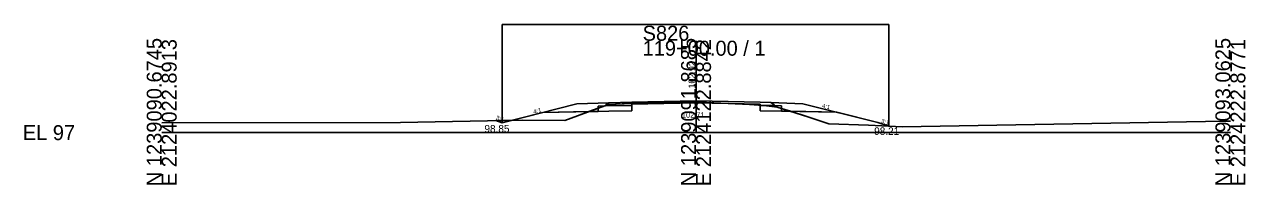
# Model space of a CAD drawing. Extents: x 2119282 to 2119710, y 1215030 to 1220057.
# Drawn here: x 2119381.9 to 2119610.4, y 1217530.1 to 1217560 of the extents above; entities that cross this region are included whole.
import ezdxf

# ---------------------------------------------------------------- set-up
doc = ezdxf.new("R2010")
doc.units = 0
for name, color, linetype in [('XS_CELL', 7, 'Continuous'), ('XS_M_DITCH', 7, 'Continuous'), ('XS_M_SHAPES_EARTHWORK', 7, 'Continuous'), ('XS_P_FINISHED_GRADE', 7, 'Continuous'), ('XS_P_FINISHED_GRADE_ELEV_TX', 7, 'Continuous'), ('XS_P_SUBGRADE_GRANULAR', 7, 'Continuous'), ('XS_P_SUBGRADE_PAVEMENT', 7, 'Continuous'), ('XS_P_TX_DCH', 7, 'Continuous'), ('XS_P_TX_FS_BS', 7, 'Continuous'), ('XS_X_GROUND', 7, 'Continuous'), ('XS_X_GROUND_TX', 7, 'Continuous')]:
    doc.layers.add(name, color=color, linetype=linetype)

msp = doc.modelspace()

# ---------------------------------------------------------------- linework, layer by layer
at = {"layer": 'XS_CELL'}
for p, q in [((2119507.6, 1217539.8), (2119507.6, 1217556.97)), ((2119407.6, 1217539.8), (2119507.6, 1217539.8)), ((2119507.6, 1217539.8), (2119607.6, 1217539.8))]:
    msp.add_line(p, q, dxfattribs=at)
at = {"layer": 'XS_M_DITCH'}
for p, q in [((2119471.29, 1217541.66), (2119471.29, 1217560.01)), ((2119471.29, 1217560.01), (2119543.67, 1217560.01)), ((2119543.67, 1217541.01), (2119543.67, 1217560.01))]:
    msp.add_line(p, q, dxfattribs=at)
at = {"layer": 'XS_M_SHAPES_EARTHWORK'}
for p, q in [((2119489.29, 1217544.36), (2119487.56, 1217543.74)), ((2119490.52, 1217544.79), (2119489.29, 1217544.36)), ((2119489.29, 1217543.77), (2119489.29, 1217544.36)), ((2119489.29, 1217544.36), (2119489.29, 1217543.77)), ((2119490.64, 1217544.8), (2119490.52, 1217544.79)), ((2119495.6, 1217544.9), (2119490.64, 1217544.8)), ((2119490.64, 1217544.8), (2119495.6, 1217544.9)), ((2119490.67, 1217544.85), (2119490.64, 1217544.8)), ((2119491.23, 1217545.05), (2119490.67, 1217544.85)), ((2119495.6, 1217545.25), (2119491.23, 1217545.05)), ((2119495.6, 1217543.9), (2119495.6, 1217544.9)), ((2119520.17, 1217544.89), (2119519.6, 1217544.92)), ((2119519.6, 1217544.92), (2119519.6, 1217544.9)), ((2119519.6, 1217544.9), (2119519.6, 1217543.9)), ((2119520.17, 1217544.89), (2119519.6, 1217544.9)), ((2119519.6, 1217544.9), (2119519.6, 1217543.9)), ((2119519.6, 1217544.9), (2119520.17, 1217544.89)), ((2119520.23, 1217544.89), (2119520.17, 1217544.89)), ((2119520.79, 1217544.83), (2119520.23, 1217544.89)), ((2119520.79, 1217544.83), (2119520.23, 1217544.89)), ((2119522.79, 1217544.57), (2119520.79, 1217544.83)), ((2119522.79, 1217544.57), (2119520.79, 1217544.83)), ((2119523.6, 1217544.31), (2119522.79, 1217544.57)), ((2119523.6, 1217544.31), (2119522.79, 1217544.57)), ((2119525.27, 1217543.79), (2119523.6, 1217544.31)), ((2119523.6, 1217544.31), (2119523.6, 1217543.82)), ((2119523.6, 1217543.82), (2119523.6, 1217544.31)), ((2119523.6, 1217543.82), (2119523.6, 1217544.31)), ((2119473.05, 1217542.1), (2119470.13, 1217542.04)), ((2119470.13, 1217542.04), (2119471.29, 1217541.66)), ((2119471.29, 1217541.66), (2119473.05, 1217542.1)), ((2119478.93, 1217543.57), (2119473.05, 1217542.1)), ((2119473.05, 1217542.1), (2119475.03, 1217542.13)), ((2119475.03, 1217542.13), (2119483.05, 1217542.1)), ((2119487.56, 1217543.74), (2119478.93, 1217543.57)), ((2119483.05, 1217542.1), (2119485.42, 1217542.97)), ((2119485.42, 1217542.97), (2119487.56, 1217543.74)), ((2119487.56, 1217543.74), (2119489.29, 1217543.77)), ((2119489.29, 1217543.77), (2119491.29, 1217543.81)), ((2119491.29, 1217543.81), (2119495.6, 1217543.9)), ((2119519.6, 1217543.9), (2119523.6, 1217543.82)), ((2119519.6, 1217543.9), (2119523.6, 1217543.82)), ((2119523.6, 1217543.82), (2119525.27, 1217543.79)), ((2119533.97, 1217543.61), (2119525.27, 1217543.79)), ((2119525.27, 1217543.79), (2119528.51, 1217542.75)), ((2119528.51, 1217542.75), (2119532.45, 1217541.46)), ((2119541.6, 1217541.7), (2119533.97, 1217543.61)), ((2119543.67, 1217541.01), (2119541.6, 1217541.7)), ((2119532.45, 1217541.46), (2119539.86, 1217541.18)), ((2119539.86, 1217541.18), (2119543.67, 1217541.01))]:
    msp.add_line(p, q, dxfattribs=at)
for points in [[(2119495.6, 1217544.9), (2119495.6, 1217545.15), (2119495.6, 1217545.25)], [(2119520.23, 1217544.89), (2119520.17, 1217544.89), (2119519.6, 1217544.9)]]:
    msp.add_lwpolyline(points, dxfattribs=at)
at = {"layer": 'XS_P_FINISHED_GRADE'}
for p, q in [((2119485.29, 1217545.16), (2119471.29, 1217541.66)), ((2119491.29, 1217545.4), (2119485.29, 1217545.16)), ((2119495.6, 1217545.48), (2119491.29, 1217545.4)), ((2119507.6, 1217545.72), (2119495.6, 1217545.48)), ((2119507.6, 1217545.72), (2119519.6, 1217545.48)), ((2119519.6, 1217545.48), (2119521.6, 1217545.44)), ((2119521.6, 1217545.44), (2119527.6, 1217545.2)), ((2119527.6, 1217545.2), (2119541.6, 1217541.7)), ((2119471.29, 1217541.66), (2119470.13, 1217542.04)), ((2119541.6, 1217541.7), (2119543.67, 1217541.01))]:
    msp.add_line(p, q, dxfattribs=at)
at = {"layer": 'XS_P_SUBGRADE_GRANULAR'}
for p, q in [((2119490.64, 1217544.8), (2119489.29, 1217544.75)), ((2119489.29, 1217543.77), (2119489.29, 1217544.75)), ((2119495.6, 1217543.9), (2119495.61, 1217544.9)), ((2119519.6, 1217543.9), (2119519.59, 1217544.9)), ((2119522.26, 1217544.85), (2119523.6, 1217544.79)), ((2119523.6, 1217543.82), (2119523.6, 1217544.79)), ((2119491.29, 1217543.81), (2119478.93, 1217543.57)), ((2119495.6, 1217543.9), (2119491.29, 1217543.81)), ((2119519.6, 1217543.9), (2119523.6, 1217543.82)), ((2119523.6, 1217543.82), (2119533.97, 1217543.61))]:
    msp.add_line(p, q, dxfattribs=at)
at = {"layer": 'XS_P_SUBGRADE_PAVEMENT'}
for p, q in [((2119490.79, 1217545.05), (2119490.64, 1217544.8)), ((2119495.61, 1217544.9), (2119490.64, 1217544.8)), ((2119491.29, 1217545.4), (2119490.79, 1217545.05)), ((2119507.6, 1217545.39), (2119495.61, 1217545.15)), ((2119495.61, 1217544.9), (2119495.61, 1217545.15)), ((2119507.6, 1217545.39), (2119519.6, 1217545.15)), ((2119519.59, 1217544.9), (2119519.6, 1217545.15)), ((2119519.59, 1217544.9), (2119522.26, 1217544.85)), ((2119521.6, 1217545.44), (2119522.11, 1217545.1)), ((2119522.11, 1217545.1), (2119522.26, 1217544.85))]:
    msp.add_line(p, q, dxfattribs=at)
at = {"layer": 'XS_X_GROUND'}
for p, q in [((2119485.42, 1217542.97), (2119491.23, 1217545.05)), ((2119491.23, 1217545.05), (2119496.32, 1217545.28)), ((2119496.32, 1217545.28), (2119507.6, 1217545.51)), ((2119507.6, 1217545.51), (2119508.25, 1217545.52)), ((2119508.25, 1217545.52), (2119517.59, 1217545.03)), ((2119517.59, 1217545.03), (2119520.17, 1217544.89)), ((2119520.17, 1217544.89), (2119520.79, 1217544.83)), ((2119520.79, 1217544.83), (2119522.79, 1217544.57)), ((2119522.79, 1217544.57), (2119528.51, 1217542.75)), ((2119407.6, 1217541.65), (2119452.32, 1217541.72)), ((2119452.32, 1217541.72), (2119475.03, 1217542.13)), ((2119475.03, 1217542.13), (2119483.05, 1217542.1)), ((2119483.05, 1217542.1), (2119485.42, 1217542.97)), ((2119528.51, 1217542.75), (2119532.45, 1217541.46)), ((2119546.17, 1217540.9), (2119606.5, 1217541.93)), ((2119606.5, 1217541.93), (2119607.6, 1217541.95)), ((2119532.45, 1217541.46), (2119539.86, 1217541.18)), ((2119539.86, 1217541.18), (2119546.17, 1217540.9))]:
    msp.add_line(p, q, dxfattribs=at)

# ---------------------------------------------------------------- texts
at = {"layer": 'XS_CELL'}
for s, p in [('S826', (2119497.6, 1217556.97)), ('119+00.00 / 1', (2119497.6, 1217554.17)), ('EL 97', (2119381.6, 1217538.4))]:
    msp.add_text(s, height=2.8, dxfattribs=at).set_placement(p)
for s, p in [('N 1239090.6745', (2119407.6, 1217529.8)), ('E 2124022.8913', (2119410.4, 1217529.8)), ('N 1239091.8685', (2119507.6, 1217529.8)), ('E 2124122.8842', (2119510.4, 1217529.8)), ('N 1239093.0625', (2119607.6, 1217529.8)), ('E 2124222.8771', (2119610.4, 1217529.8))]:
    msp.add_text(s, height=2.8, rotation=90, dxfattribs=at).set_placement(p)
at = {"layer": 'XS_P_FINISHED_GRADE_ELEV_TX'}
msp.add_text('102.92', height=1.25, rotation=90, dxfattribs=at).set_placement((2119507.45, 1217548.04))
at = {"layer": 'XS_P_TX_DCH'}
for s, p in [('98.85', (2119468, 1217539.84)), ('98.21', (2119540.94, 1217539.38))]:
    msp.add_text(s, height=1.4, dxfattribs=at).set_placement(p)
at = {"layer": 'XS_P_TX_FS_BS'}
for s, rotation, p in [('4:1', 14.0362, (2119477.24, 1217543.31)), ('4:1', 345.9638, (2119531.11, 1217544.5)), ('3:1', 341.5651, (2119470.07, 1217542.27)), ('3:1', 341.5651, (2119542.15, 1217541.69))]:
    msp.add_text(s, height=0.8, rotation=rotation, dxfattribs=at).set_placement(p)
at = {"layer": 'XS_X_GROUND_TX'}
msp.add_text('102.71', height=1, dxfattribs=at).set_placement((2119504.96, 1217542.61))

doc.saveas('drawing.dxf')
